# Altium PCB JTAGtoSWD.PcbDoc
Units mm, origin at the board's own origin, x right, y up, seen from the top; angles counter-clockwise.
Board outline 27.5 x 33.5 mm, 2 copper layers (Top Layer, Bottom Layer); 3 components, 0 nets, 44 pads, 0 vias.
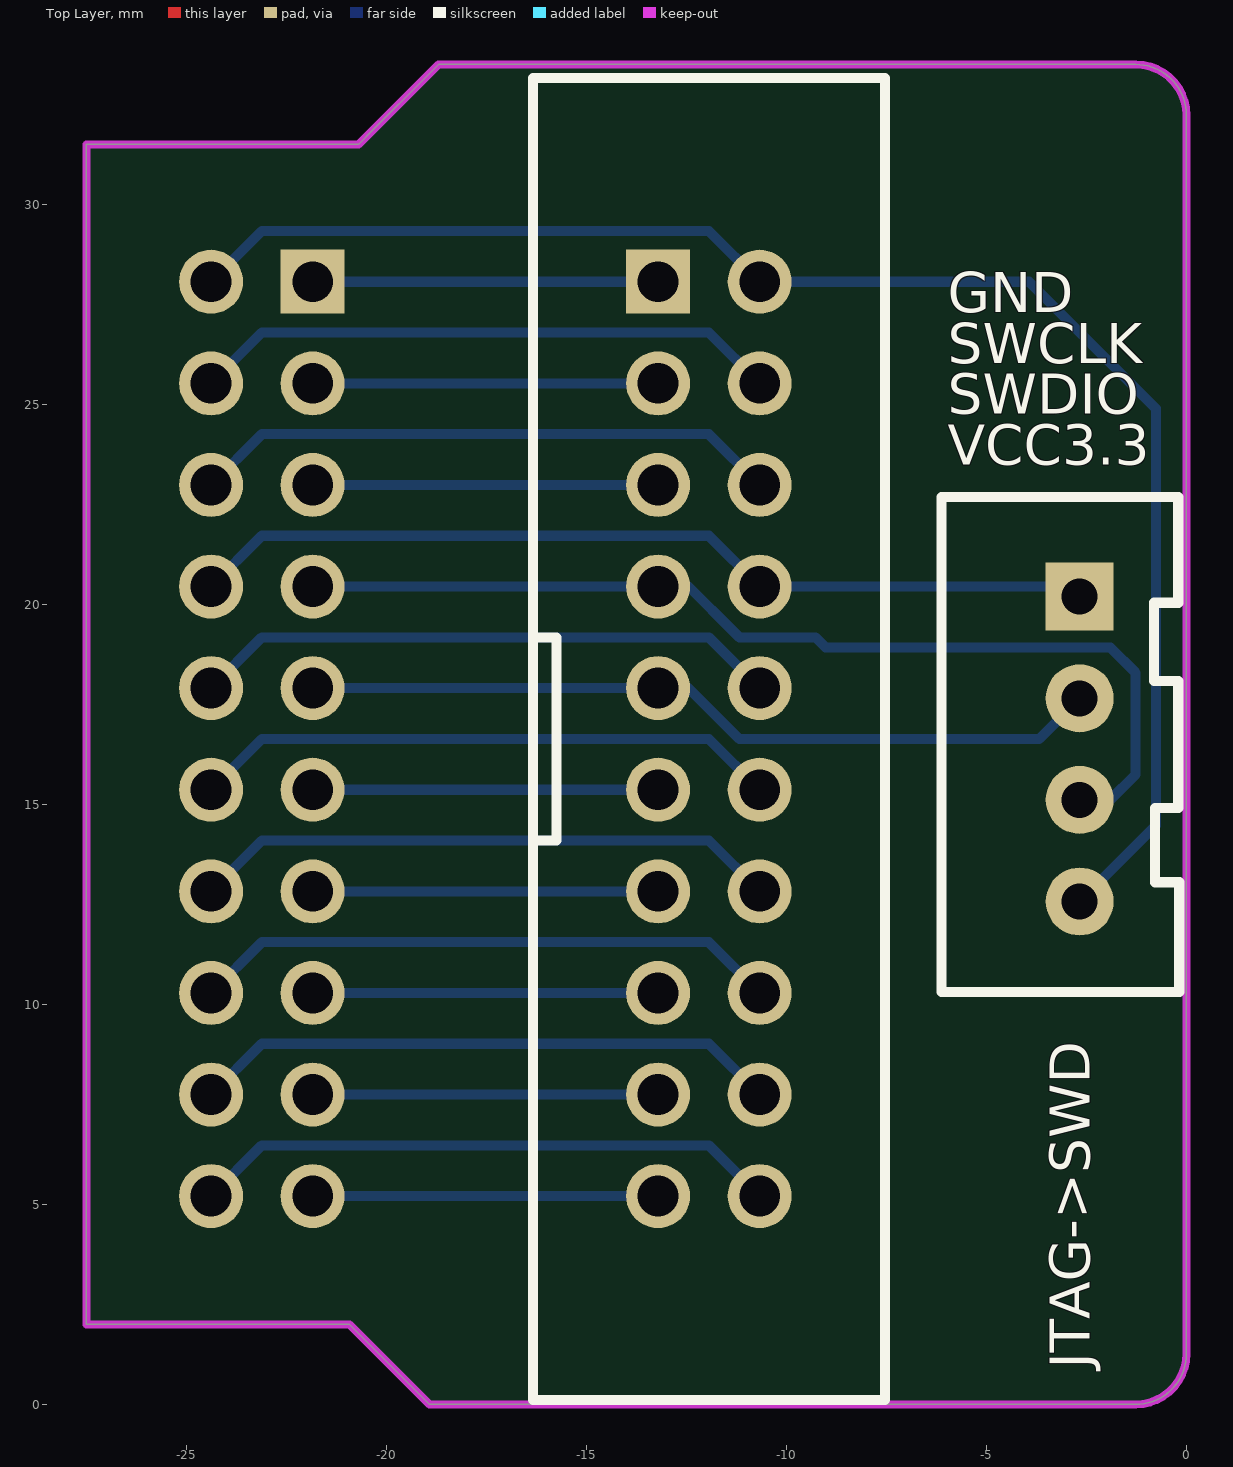
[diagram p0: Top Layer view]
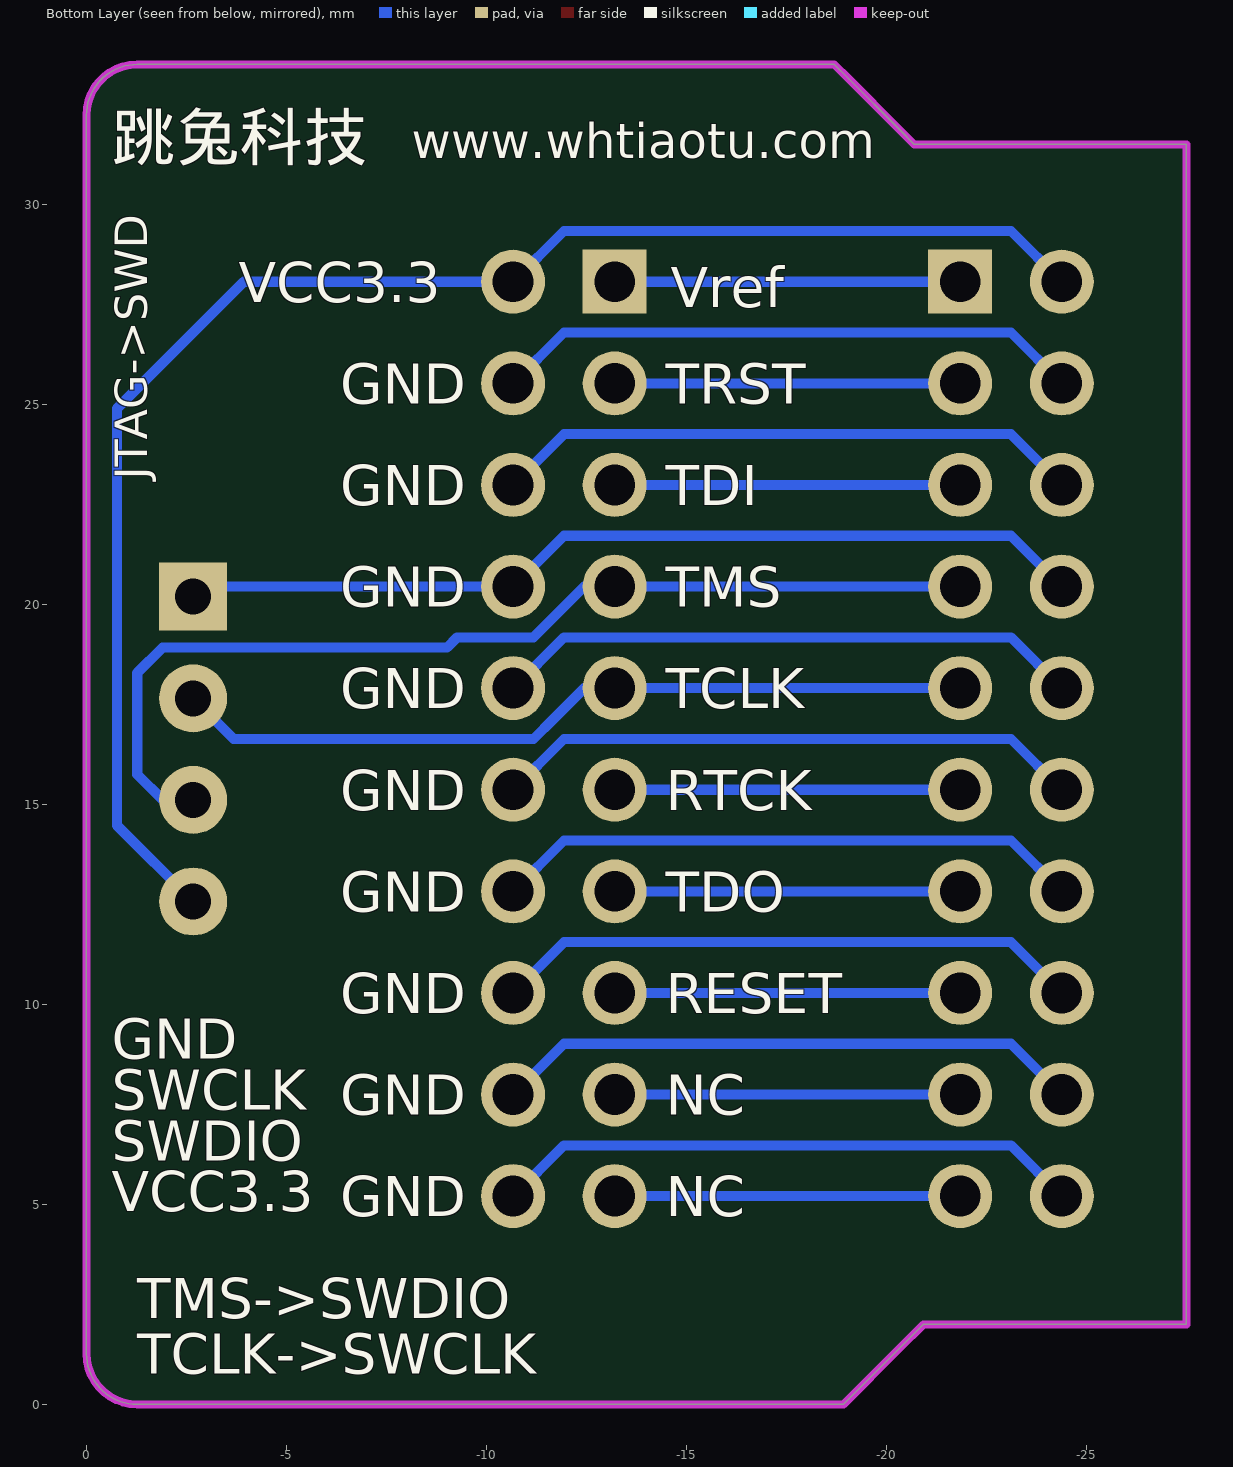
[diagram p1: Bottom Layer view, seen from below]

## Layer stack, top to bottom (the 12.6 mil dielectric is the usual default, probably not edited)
Top Solder: solder mask 0.0102, Solder Resist, Dk 3.5
Top Layer: signal copper 0.0356
Dielectric 1: dielectric 0.32, FR-4, Dk 4.8
Bottom Layer: signal copper 0.0356
Bottom Solder: solder mask 0.0102, Solder Resist, Dk 3.5

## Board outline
-27.5,2 -20.923,2 -20.32,1.397 -18.923,0 -1.27,0 ccw(c-1.27,1.27) 0,1.27 0,32.23 ccw(c-1.27,32.23) -1.27,33.5 -18.697,33.5 -19.05,33.147 -20.32,31.877 -20.697,31.5 -27.5,31.5

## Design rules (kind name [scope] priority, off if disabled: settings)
Clearance [All] p1: gap=0.254 ignorepadtopadclearanceinfootprint=FALSE except(0: Arc-Hole Track-Hole SMDPad-Hole THPad-Hole Via-Hole Fill-Hole Poly-Hole Region-Hole Text-Hole)
PolygonConnect [All] p1: connectstyle=Relief reliefconductorwidth=0.254 reliefentries=4 polygonreliefangle="90 Angle" airgapwidth=0.254
RoutingVias [All] p1: holewidth=0.711 width=1.27 viastyle="Through Hole" minholewidth=0.711 minwidth=1.27 maxholewidth=0.711 maxwidth=1.27
SolderMaskExpansion [All] p1: expansion=0.102
Width [All] p1: maxlimit=0.254 minlimit=0.254 preferedwidth=0.254
30 further rules are at their usual default settings.

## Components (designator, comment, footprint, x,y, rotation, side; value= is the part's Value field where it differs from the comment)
? "Comment" DC-2.54-L-Z-20P -11.938,16.637 r270 top locked
? "Comment" XH2.54-LI-4P -2.667,16.383 r270 top locked
? "Comment" DC-2.54-L-Z-20P -23.114,16.637 r270 bottom locked

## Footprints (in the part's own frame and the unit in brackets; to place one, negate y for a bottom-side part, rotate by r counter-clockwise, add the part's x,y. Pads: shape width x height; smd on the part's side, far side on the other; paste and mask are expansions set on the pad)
DC-2.54-L-Z-20P [mm]
  rect 1.6x1.6 hole 1.02: 1(-11.43,-1.27)
  round 1.6 hole 1.02: 2(-11.43,1.27) 3(-8.89,-1.27) 4(-8.89,1.27) 5(-6.35,-1.27) 6(-6.35,1.27) 7(-3.81,-1.27) 8(-3.81,1.27) 9(-1.27,-1.27) 10(-1.27,1.27) 11(1.27,-1.27) 12(1.27,1.27) 13(3.81,-1.27) 14(3.81,1.27) 15(6.35,-1.27) 16(6.35,1.27) 17(8.89,-1.27) 18(8.89,1.27) 19(11.43,-1.27) 20(11.43,1.27)
  silkscreen extent -16.52,-4.4 16.53,4.4, body extent -16.52,-4.4 16.53,4.7, height 8.8
XH2.54-LI-4P [mm]
  rect 1.7x1.7 hole 0.9: 1(-3.81,0)
  round 1.7 hole 0.9: 2(-1.27,0) 3(1.27,0) 4(3.81,0)
  silkscreen extent -6.3,-3.45 6.07,2.49, body extent -6.31,-3.3 6.31,2.4, height 7.03

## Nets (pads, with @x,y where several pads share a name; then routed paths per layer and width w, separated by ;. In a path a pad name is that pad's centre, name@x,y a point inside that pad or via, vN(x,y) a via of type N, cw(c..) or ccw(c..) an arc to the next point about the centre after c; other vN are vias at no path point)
pads on no net: ?.1 ?.2 ?.3 ?.4 ?.5 ?.6 ?.7 ?.8 ?.9 ?.10 ?.11 ?.12 ?.13 ?.14 ?.15 ?.16 ?.17 ?.18 ?.19 ?.20
copper on no net: | length 296
  Bottom Layer w0.254: -24.384,5.207 -23.114,6.477 -11.938,6.477 -10.668,5.207 ; -24.384,7.747 -23.114,9.017 -11.938,9.017 -10.668,7.747 ; -24.384,10.287 -23.114,11.557 -11.938,11.557 -10.668,10.287 ; -24.384,12.827 -23.114,14.097 -11.938,14.097 -10.668,12.827 -10.414,12.573 ; -24.384,15.367 -23.114,16.637 -11.938,16.637 -10.668,15.367 ; -24.384,17.907 -23.114,19.177 -11.938,19.177 -10.668,17.907 ; -24.384,20.447 -23.114,21.717 -11.938,21.717 -10.668,20.447 -2.921,20.447 -2.667,20.193 ; -24.384,22.987 -23.114,24.257 -11.938,24.257 -10.668,22.987 ; -24.384,25.527 -23.114,26.797 -11.938,26.797 -10.668,25.527 ; -24.384,28.067 -23.114,29.337 -21.463,29.337 -11.938,29.337 -10.668,28.067 -3.937,28.067 -0.762,24.892 -0.762,14.478 -2.667,12.573 ; -21.844,5.207 -13.208,5.207 ; -21.844,7.747 -13.208,7.747 ; -21.844,10.287 -13.208,10.287 ; -21.844,12.827 -13.208,12.827 ; -21.844,15.367 -13.208,15.367 ; -21.844,17.907 -13.208,17.907 -12.446,17.907 -11.684,17.145 -11.176,16.637 -9.652,16.637 -9.271,16.637 -3.683,16.637 -2.667,17.653 -3.302,17.653 ; -21.844,20.447 -13.208,20.447 -12.446,20.447 -11.303,19.304 -11.176,19.177 -9.271,19.177 -9.017,18.923 -4.953,18.923 -1.905,18.923 -1.27,18.288 -1.27,15.748 -1.905,15.113 -2.667,15.113 ; -21.844,22.987 -13.208,22.987 ; -21.844,25.527 -13.208,25.527 ; -21.844,28.067 -13.208,28.067

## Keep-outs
Keep-Out Layer:
  the board outline again, w0.203

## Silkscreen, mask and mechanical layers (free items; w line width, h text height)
Top Overlay:
  text "GND" at -5.969,27.305 h1
  text "SWCLK" at -5.969,26.035 h1
  text "SWDIO" at -5.969,24.765 h1
  text "VCC3.3" at -5.969,23.495 h1
  text "JTAG->SWD" at -2.413,0.889 h1 r90
Bottom Overlay:
  text "www.whtiaotu.com" at -8.128,30.861 h1.5
  text "跳兔科技" at -0.635,30.734 h2
  text "VCC3.3" at -3.81,27.559 h1
  text "Vref" at -14.605,27.432 h1
  text "TRST" at -14.478,25.019 h1
  text "GND" at -6.35,25.019 h1
  text "JTAG->SWD" at -1.524,23.114 h0.81 r270
  text "TDI" at -14.478,22.479 h1
  text "GND" at -6.35,22.479 h1
  text "TMS" at -14.478,19.939 h1
  text "GND" at -6.35,19.939 h1
  text "TCLK" at -14.478,17.399 h1
  text "GND" at -6.35,17.399 h1
  text "RTCK" at -14.478,14.859 h1
  text "GND" at -6.35,14.859 h1
  text "TDO" at -14.478,12.319 h1
  text "GND" at -6.35,12.319 h1
  text "RESET" at -14.478,9.779 h1
  text "GND" at -6.35,9.779 h1
  text "GND" at -0.635,8.636 h1
  text "SWCLK" at -0.635,7.366 h1
  text "NC" at -14.478,7.239 h1
  text "GND" at -6.35,7.239 h1
  text "SWDIO" at -0.635,6.096 h1
  text "VCC3.3" at -0.635,4.826 h1
  text "NC" at -14.478,4.699 h1
  text "GND" at -6.35,4.699 h1
  text "TMS->SWDIO" at -1.27,2.159 h1
  text "TCLK->SWCLK" at -1.27,0.762 h1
